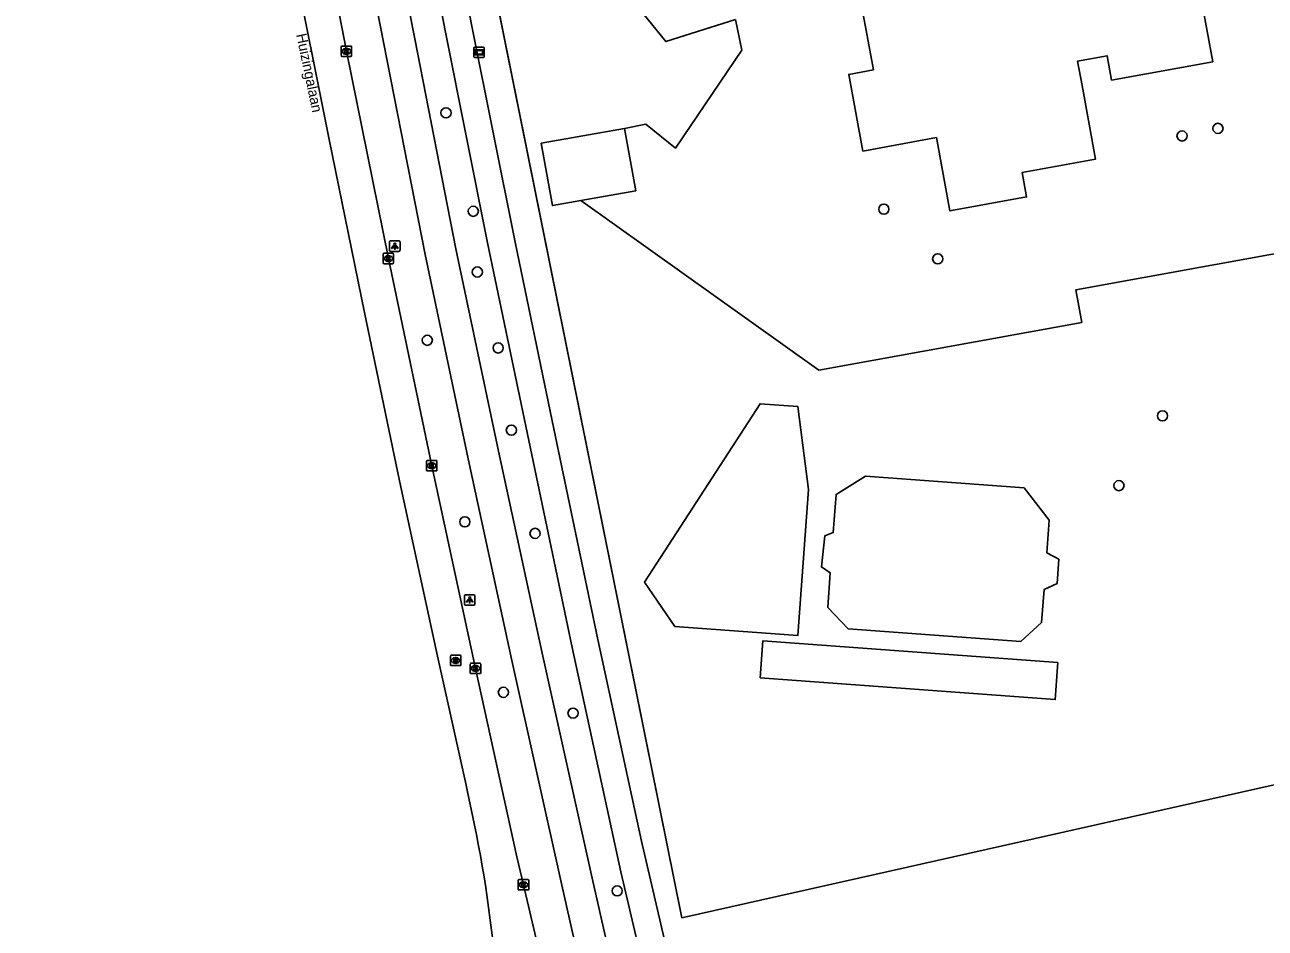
# Model space of a CAD drawing. Extents: x 159451 to 160663, y 388402 to 389723.
# Drawn here: x 159499.2 to 159618.7, y 388755.7 to 388842.8 of the extents above; entities that cross this region are included whole.
import ezdxf

# ---------------------------------------------------------------- set-up
doc = ezdxf.new("R2010")
doc.units = 0
for name, color, linetype in [('IMGEO_Boom', 7, 'Continuous'), ('IMGEO_Erf', 7, 'Continuous'), ('IMGEO_Fietspad_gesloten', 7, 'Continuous'), ('IMGEO_Groenvoorziening', 7, 'Continuous'), ('IMGEO_Hek', 7, 'Continuous'), ('IMGEO_Kolk', 7, 'Continuous'), ('IMGEO_Lichtpunt', 7, 'Continuous'), ('IMGEO_Loofbos', 7, 'Continuous'), ('IMGEO_Openbare_ruimte_label', 7, 'Continuous'), ('IMGEO_OVBaan_gesloten', 7, 'Continuous'), ('IMGEO_Pand', 7, 'Continuous'), ('IMGEO_Rijbaan_regionaal_gesloten', 7, 'Continuous'), ('IMGEO_Rioolput', 7, 'Continuous'), ('IMGEO_Terreindeel_zand', 7, 'Continuous'), ('IMGEO_Verklikker', 7, 'Continuous'), ('IMGEO_Voetpad_open', 7, 'Continuous')]:
    doc.layers.add(name, color=color, linetype=linetype)

msp = doc.modelspace()

# ---------------------------------------------------------------- linework, layer by layer
at = {"layer": 'IMGEO_Boom'}
for centre in [(159539.81, 388834.33), (159614.19, 388832.83), (159610.73, 388832.1), (159542.44, 388824.84), (159582, 388825.05), (159587.19, 388820.26), (159542.83, 388818.99), (159538.01, 388812.41), (159544.83, 388811.67), (159608.84, 388805.12), (159546.11, 388803.74), (159604.65, 388798.4), (159541.62, 388794.91), (159548.39, 388793.8), (159545.34, 388778.48), (159552.05, 388776.48), (159556.31, 388759.34)]:
    msp.add_circle(centre, 0.489, dxfattribs=at)
at = {"layer": 'IMGEO_Erf'}
for points in [[(159597.7, 388791.94), (159598.86, 388791.3), (159598.71, 388788.98), (159597.43, 388788.39), (159597.2, 388785.2), (159595.21, 388783.38), (159578.57, 388784.61), (159576.6, 388786.67), (159576.84, 388790.01), (159575.99, 388790.57), (159576.32, 388793.57), (159577.13, 388793.87), (159577.4, 388797.55), (159580.22, 388799.32), (159595.51, 388798.19), (159597.93, 388795.08), (159597.7, 388791.94)], [(159598.77, 388781.35), (159598.51, 388777.78), (159570.09, 388779.88), (159570.35, 388783.45), (159598.77, 388781.35)]]:
    msp.add_lwpolyline(points, dxfattribs=at)
at = {"layer": 'IMGEO_Fietspad_gesloten'}
for points in [[(159511.08, 388964.83), (159511.9, 388959.73), (159512.11, 388958.35), (159516.59, 388932.87), (159519.02, 388919.06), (159522.62, 388899.25), (159526.35, 388879.41), (159530.09, 388859.95), (159533.81, 388840.97), (159537.8, 388820.69), (159541.95, 388800.98), (159546.15, 388781.55), (159550.97, 388759.91), (159555.06, 388741.81), (159559.07, 388724.6), (159563.77, 388704.28), (159564.81, 388699.67)], [(159567.82, 388699.99), (159566.81, 388704.48), (159562.68, 388722.31), (159558.53, 388740.16), (159553.91, 388760.57), (159549.09, 388782.26), (159544.88, 388801.72), (159540.76, 388821.22), (159536.81, 388841.45), (159533.29, 388859.39), (159529.26, 388880.34), (159525.53, 388900.16), (159521.97, 388919.7), (159518.43, 388939.84), (159516.78, 388949.35), (159515.14, 388958.74), (159514.42, 388963.29)]]:
    msp.add_lwpolyline(points, dxfattribs=at)
at = {"layer": 'IMGEO_Groenvoorziening'}
msp.add_lwpolyline([(159574.74, 388798.04), (159573.7, 388783.95), (159561.86, 388784.82), (159558.95, 388789.11), (159570.07, 388806.3), (159573.7, 388806.03), (159574.74, 388798.04)], dxfattribs=at)
at = {"layer": 'IMGEO_Hek'}
msp.add_lwpolyline([(159678.25, 388782.74), (159562.53, 388756.76), (159538.54, 388875.75), (159538.12, 388877.8), (159532.82, 388904.1), (159527.33, 388934.89), (159516.65, 389000), (159504.91, 389075.55), (159505.31, 389078.14), (159506.99, 389079.73), (159534.92, 389087.14), (159543.41, 389088.84), (159556.65, 389090.59), (159574.7, 389093.29)], dxfattribs=at)
at = {"layer": 'IMGEO_Kolk'}
for p, q in [((159529.72, 388839.84), (159529.72, 388840.69)), ((159529.79, 388840.76), (159530.64, 388840.76)), ((159530.21, 388840.54), (159530.23, 388840.54)), ((159530.72, 388840.69), (159530.72, 388839.84)), ((159530.64, 388839.76), (159529.79, 388839.76)), ((159530.23, 388839.98), (159530.2, 388839.98)), ((159533.76, 388819.87), (159533.76, 388820.72)), ((159533.83, 388820.79), (159534.69, 388820.79)), ((159534.25, 388820.57), (159534.27, 388820.57)), ((159534.76, 388820.72), (159534.76, 388819.87)), ((159534.69, 388819.79), (159533.83, 388819.79)), ((159534.27, 388820.01), (159534.24, 388820.01)), ((159537.94, 388799.89), (159537.94, 388800.75)), ((159538.01, 388800.82), (159538.87, 388800.82)), ((159538.87, 388799.82), (159538.01, 388799.82)), ((159538.45, 388800.04), (159538.42, 388800.04)), ((159538.43, 388800.6), (159538.45, 388800.6)), ((159538.94, 388800.75), (159538.94, 388799.89)), ((159542.15, 388780.35), (159542.15, 388781.21)), ((159542.23, 388781.28), (159543.08, 388781.28)), ((159542.64, 388781.06), (159542.67, 388781.06)), ((159543.16, 388781.21), (159543.16, 388780.35)), ((159543.08, 388780.28), (159542.23, 388780.28)), ((159542.66, 388780.5), (159542.64, 388780.5)), ((159546.78, 388759.5), (159546.78, 388760.35)), ((159546.85, 388760.43), (159547.71, 388760.43)), ((159547.78, 388760.35), (159547.78, 388759.5)), ((159547.71, 388759.43), (159546.85, 388759.43)), ((159547.29, 388759.65), (159547.26, 388759.65)), ((159547.27, 388760.21), (159547.29, 388760.21))]:
    msp.add_line(p, q, dxfattribs=at)
for points in [[(159529.72, 388839.84), (159529.72, 388840.69)], [(159529.79, 388840.76), (159530.64, 388840.76)], [(159530.04, 388840.46), (159530.16, 388840.46), (159530.16, 388840.31), (159530.29, 388840.46), (159530.46, 388840.46), (159530.31, 388840.31), (159530.46, 388840.06), (159530.31, 388840.06), (159530.23, 388840.23), (159530.16, 388840.16), (159530.16, 388840.06), (159530.04, 388840.06), (159530.04, 388840.46)], [(159530.72, 388840.69), (159530.72, 388839.84)], [(159530.64, 388839.76), (159529.79, 388839.76)], [(159533.76, 388819.87), (159533.76, 388820.72)], [(159533.83, 388820.79), (159534.69, 388820.79)], [(159534.08, 388820.49), (159534.2, 388820.49), (159534.2, 388820.34), (159534.33, 388820.49), (159534.5, 388820.49), (159534.35, 388820.34), (159534.5, 388820.09), (159534.35, 388820.09), (159534.27, 388820.26), (159534.2, 388820.19), (159534.2, 388820.09), (159534.08, 388820.09), (159534.08, 388820.49)], [(159534.76, 388820.72), (159534.76, 388819.87)], [(159534.69, 388819.79), (159533.83, 388819.79)], [(159537.94, 388799.89), (159537.94, 388800.75)], [(159538.01, 388800.82), (159538.87, 388800.82)], [(159538.87, 388799.82), (159538.01, 388799.82)], [(159538.26, 388800.52), (159538.38, 388800.52), (159538.38, 388800.37), (159538.51, 388800.52), (159538.68, 388800.52), (159538.53, 388800.37), (159538.68, 388800.12), (159538.53, 388800.12), (159538.45, 388800.28), (159538.38, 388800.22), (159538.38, 388800.12), (159538.26, 388800.12), (159538.26, 388800.52)], [(159538.94, 388800.75), (159538.94, 388799.89)], [(159542.15, 388780.35), (159542.15, 388781.21)], [(159542.23, 388781.28), (159543.08, 388781.28)], [(159542.47, 388780.98), (159542.6, 388780.98), (159542.6, 388780.83), (159542.73, 388780.98), (159542.89, 388780.98), (159542.75, 388780.83), (159542.9, 388780.58), (159542.75, 388780.58), (159542.66, 388780.75), (159542.6, 388780.68), (159542.6, 388780.58), (159542.47, 388780.58), (159542.47, 388780.98)], [(159543.16, 388781.21), (159543.16, 388780.35)], [(159543.08, 388780.28), (159542.23, 388780.28)], [(159546.78, 388759.5), (159546.78, 388760.35)], [(159546.85, 388760.43), (159547.71, 388760.43)], [(159547.78, 388760.35), (159547.78, 388759.5)], [(159547.71, 388759.43), (159546.85, 388759.43)], [(159547.1, 388760.13), (159547.22, 388760.13), (159547.22, 388759.98), (159547.35, 388760.13), (159547.52, 388760.13), (159547.37, 388759.98), (159547.52, 388759.73), (159547.37, 388759.73), (159547.29, 388759.89), (159547.22, 388759.83), (159547.22, 388759.73), (159547.1, 388759.73), (159547.1, 388760.13)]]:
    msp.add_lwpolyline(points, dxfattribs=at)
for centre, start, end in [((159529.79, 388840.69), 91.552, 178.448), ((159529.79, 388840.69), 91.552, 178.448), ((159530.64, 388840.69), 1.552, 88.448), ((159530.64, 388840.69), 1.552, 88.448), ((159529.79, 388839.84), 181.552, 268.448), ((159529.79, 388839.84), 181.552, 268.448), ((159530.64, 388839.84), 271.552, 358.448), ((159530.64, 388839.84), 271.552, 358.448), ((159533.83, 388820.72), 91.552, 178.448), ((159533.83, 388820.72), 91.552, 178.448), ((159534.68, 388820.72), 1.552, 88.448), ((159534.68, 388820.72), 1.552, 88.448), ((159533.83, 388819.87), 181.552, 268.448), ((159533.83, 388819.87), 181.552, 268.448), ((159534.68, 388819.87), 271.552, 358.448), ((159534.68, 388819.87), 271.552, 358.448), ((159538.02, 388800.74), 91.552, 178.448), ((159538.02, 388800.74), 91.552, 178.448), ((159538.02, 388799.89), 181.552, 268.448), ((159538.02, 388799.89), 181.552, 268.448), ((159538.86, 388800.74), 1.552, 88.448), ((159538.86, 388800.74), 1.552, 88.448), ((159538.86, 388799.89), 271.552, 358.448), ((159538.86, 388799.89), 271.552, 358.448), ((159542.23, 388781.21), 91.552, 178.448), ((159542.23, 388781.21), 91.552, 178.448), ((159543.08, 388781.21), 1.552, 88.448), ((159543.08, 388781.21), 1.552, 88.448), ((159542.23, 388780.36), 181.552, 268.448), ((159542.23, 388780.36), 181.552, 268.448), ((159543.08, 388780.36), 271.552, 358.448), ((159543.08, 388780.36), 271.552, 358.448), ((159546.85, 388760.35), 91.552, 178.448), ((159546.85, 388760.35), 91.552, 178.448), ((159547.7, 388760.35), 1.552, 88.448), ((159547.7, 388760.35), 1.552, 88.448), ((159546.85, 388759.5), 181.552, 268.448), ((159546.85, 388759.5), 181.552, 268.448), ((159547.7, 388759.5), 271.552, 358.448), ((159547.7, 388759.5), 271.552, 358.448)]:
    msp.add_arc(centre, 0.0765, start, end, dxfattribs=at)
for centre, major_axis, ratio, start_param, end_param in [((159530.2, 388840.26), (-0.387, 0.002), 0.722429, 4.712389, 7.853982), ((159530.23, 388840.26), (-0.39, 0.002), 0.717154, 1.570796, 4.712389), ((159534.25, 388820.29), (-0.387, 0.002), 0.722429, 4.712389, 7.853982), ((159534.27, 388820.29), (-0.39, 0.002), 0.717154, 1.570796, 4.712389), ((159538.43, 388800.32), (-0.387, 0.002), 0.722429, 4.712389, 7.853982), ((159538.45, 388800.32), (-0.39, 0.002), 0.717154, 1.570796, 4.712389), ((159542.64, 388780.78), (-0.387, 0.002), 0.722429, 4.712389, 7.853982), ((159542.67, 388780.78), (-0.39, 0.002), 0.717154, 1.570796, 4.712389), ((159547.27, 388759.93), (-0.387, 0.002), 0.722429, 4.712389, 7.853982), ((159547.29, 388759.93), (-0.39, 0.002), 0.717154, 1.570796, 4.712389)]:
    msp.add_ellipse(centre, major_axis=major_axis, ratio=ratio, start_param=start_param, end_param=end_param, dxfattribs=at)
at = {"layer": 'IMGEO_Lichtpunt'}
for p, q in [((159534.38, 388821.89), (159534.38, 388821.08)), ((159534.38, 388821.89), (159534.38, 388821.08)), ((159535.28, 388821.98), (159534.47, 388821.98)), ((159535.28, 388821.98), (159534.47, 388821.98)), ((159535.38, 388821.08), (159535.38, 388821.89)), ((159535.38, 388821.08), (159535.38, 388821.89)), ((159534.47, 388820.98), (159535.28, 388820.98)), ((159534.47, 388820.98), (159535.28, 388820.98)), ((159541.6, 388787.79), (159541.6, 388786.99)), ((159541.6, 388787.79), (159541.6, 388786.99)), ((159542.5, 388787.89), (159541.69, 388787.89)), ((159542.5, 388787.89), (159541.69, 388787.89)), ((159542.59, 388786.99), (159542.59, 388787.79)), ((159542.59, 388786.99), (159542.59, 388787.79)), ((159541.69, 388786.89), (159542.5, 388786.89)), ((159541.69, 388786.89), (159542.5, 388786.89))]:
    msp.add_line(p, q, dxfattribs=at)
for points in [[(159534.75, 388821.55), (159534.79, 388821.52), (159534.61, 388821.26), (159534.57, 388821.29), (159534.75, 388821.55)], [(159534.86, 388821.5), (159534.9, 388821.5), (159534.9, 388821.18), (159534.86, 388821.18), (159534.86, 388821.5)], [(159534.97, 388821.52), (159535, 388821.55), (159535.19, 388821.29), (159535.15, 388821.26), (159534.97, 388821.52)], [(159541.97, 388787.46), (159542.01, 388787.43), (159541.82, 388787.17), (159541.78, 388787.19), (159541.97, 388787.46)], [(159542.07, 388787.41), (159542.12, 388787.41), (159542.12, 388787.09), (159542.07, 388787.09), (159542.07, 388787.41)], [(159542.18, 388787.43), (159542.22, 388787.46), (159542.41, 388787.19), (159542.37, 388787.17), (159542.18, 388787.43)]]:
    msp.add_lwpolyline(points, dxfattribs=at)
for centre in [(159534.88, 388821.68), (159542.1, 388787.59)]:
    msp.add_circle(centre, 0.0994, dxfattribs=at)
for centre, start, end in [((159534.47, 388821.89), 90, 180), ((159534.47, 388821.89), 90, 180), ((159535.28, 388821.89), 0, 90), ((159535.28, 388821.89), 0, 90), ((159534.47, 388821.08), 180, 270), ((159534.47, 388821.08), 180, 270), ((159535.28, 388821.08), 270, 0), ((159535.28, 388821.08), 270, 360), ((159541.69, 388787.79), 90, 180), ((159541.69, 388787.79), 90, 180), ((159542.5, 388787.79), 0, 90), ((159542.5, 388787.79), 0, 90), ((159541.69, 388786.99), 180, 270), ((159541.69, 388786.99), 180, 270), ((159542.5, 388786.99), 270, 0), ((159542.5, 388786.99), 270, 360)]:
    msp.add_arc(centre, 0.0946, start, end, dxfattribs=at)
at = {"layer": 'IMGEO_Loofbos'}
msp.add_lwpolyline([(159538.55, 388875.67), (159562.53, 388756.76), (159678.25, 388782.74), (159689.42, 388833.24), (159688.56, 388837.48), (159685.61, 388852.04)], dxfattribs=at)
at = {"layer": 'IMGEO_OVBaan_gesloten'}
for points in [[(159499.23, 388994.84), (159500.03, 388990.58), (159500.27, 388989.26), (159503.76, 388967.73), (159507.6, 388945.01), (159510.84, 388926.49), (159514.58, 388905.28), (159517.66, 388888.54), (159521.55, 388867.6), (159524.96, 388849.75), (159528.54, 388831.76), (159531.95, 388815.1), (159535.34, 388798.85), (159538.98, 388781.96), (159541.75, 388769.52)], [(159543.64, 388759.66), (159544.31, 388754.59)]]:
    msp.add_lwpolyline(points, dxfattribs=at)
msp.add_arc((159393.65, 388735.92), 151.86, 8.996, 12.7816, dxfattribs=at)
at = {"layer": 'IMGEO_Pand'}
for points in [[(159612.61, 388845.16), (159613.69, 388839.26), (159603.94, 388837.48), (159603.51, 388839.83), (159600.67, 388839.31), (159601.1, 388836.96), (159602.4, 388829.87), (159595.32, 388828.57), (159595.75, 388826.23), (159588.36, 388824.87), (159587.06, 388831.95), (159579.98, 388830.65), (159578.62, 388838.04), (159580.99, 388838.48), (159579.69, 388845.56)], [(159552.81, 388825.88), (159550.06, 388825.39), (159548.99, 388831.4), (159557.02, 388832.83)], [(159557.02, 388832.83), (159558.09, 388826.82), (159552.81, 388825.88)]]:
    msp.add_lwpolyline(points, dxfattribs=at)
at = {"layer": 'IMGEO_Rijbaan_regionaal_gesloten'}
msp.add_lwpolyline([(159561.59, 388698.98), (159561.07, 388701.2), (159560.62, 388703.15), (159556.37, 388721.14), (159551.72, 388741.02), (159547.28, 388759.93), (159546.64, 388762.61), (159542.65, 388780.78), (159538.44, 388800.32), (159534.26, 388820.29), (159530.22, 388840.26), (159526.53, 388859.3), (159522.9, 388878.37), (159519.19, 388898.44), (159515.61, 388918.53), (159512.08, 388938.65), (159508.7, 388957.75), (159508.35, 388959.87), (159507.46, 388965.11)], dxfattribs=at)
at = {"layer": 'IMGEO_Rioolput'}
for p, q in [((159540.24, 388781.13), (159540.24, 388781.98)), ((159540.32, 388782.06), (159541.17, 388782.06)), ((159540.73, 388781.83), (159540.76, 388781.83)), ((159541.24, 388781.98), (159541.24, 388781.13)), ((159541.17, 388781.05), (159540.32, 388781.05)), ((159540.75, 388781.28), (159540.73, 388781.28))]:
    msp.add_line(p, q, dxfattribs=at)
for points in [[(159540.24, 388781.13), (159540.24, 388781.98)], [(159540.32, 388782.06), (159541.17, 388782.06)], [(159541.24, 388781.98), (159541.24, 388781.13)], [(159541.17, 388781.05), (159540.32, 388781.05)], [(159540.83, 388781.75), (159540.58, 388781.75), (159540.58, 388781.35)], [(159540.58, 388781.35), (159540.7, 388781.35), (159540.7, 388781.52), (159540.71, 388781.52)], [(159540.76, 388781.67), (159540.7, 388781.67), (159540.7, 388781.59)], [(159540.7, 388781.59), (159540.75, 388781.59)], [(159540.76, 388781.49), (159540.83, 388781.35), (159540.97, 388781.35), (159540.91, 388781.48)]]:
    msp.add_lwpolyline(points, dxfattribs=at)
for centre, radius, start, end in [((159540.32, 388781.98), 0.0765, 91.552, 178.448), ((159540.32, 388781.98), 0.0765, 91.552, 178.448), ((159541.17, 388781.98), 0.0765, 1.552, 88.448), ((159541.17, 388781.98), 0.0765, 1.552, 88.448), ((159540.32, 388781.13), 0.0765, 181.552, 268.448), ((159540.32, 388781.13), 0.0765, 181.552, 268.448), ((159540.71, 388781.46), 0.0533, 26.0293, 88.6989), ((159540.74, 388781.78), 0.19, 274.7715, 282.9687), ((159540.76, 388781.58), 0.0964, 77.0061, 93.1865), ((159540.78, 388781.63), 0.0378, 276.6634, 79.6772), ((159540.83, 388781.64), 0.109, 350.3612, 89.416), ((159540.83, 388781.64), 0.112, 277.5842, 350.9817), ((159540.81, 388781.43), 0.108, 29.5134, 73.7905), ((159541.17, 388781.13), 0.0765, 271.552, 358.448), ((159541.17, 388781.13), 0.0765, 271.552, 358.448)]:
    msp.add_arc(centre, radius, start, end, dxfattribs=at)
for centre, major_axis, ratio, start_param, end_param in [((159540.73, 388781.55), (-0.387, 0.002), 0.722429, 4.712389, 7.853982), ((159540.75, 388781.55), (-0.39, 0.002), 0.717154, 1.570796, 4.712389)]:
    msp.add_ellipse(centre, major_axis=major_axis, ratio=ratio, start_param=start_param, end_param=end_param, dxfattribs=at)
at = {"layer": 'IMGEO_Terreindeel_zand'}
msp.add_lwpolyline([(159567.72, 388843.34), (159560.98, 388841.19), (159555.74, 388847.74), (159560.59, 388852.46)], dxfattribs=at)
at = {"layer": 'IMGEO_Verklikker'}
for p, q in [((159542.5, 388839.77), (159542.5, 388840.57)), ((159542.5, 388840.57), (159542.5, 388839.77)), ((159542.6, 388840.67), (159543.39, 388840.67)), ((159543.39, 388840.67), (159542.6, 388840.67)), ((159543.49, 388840.57), (159543.49, 388839.77)), ((159543.49, 388839.77), (159543.49, 388840.57)), ((159543.39, 388839.67), (159542.6, 388839.67)), ((159542.6, 388839.67), (159543.39, 388839.67))]:
    msp.add_line(p, q, dxfattribs=at)
for points in [[(159542.6, 388840.4), (159543.39, 388840.4), (159543.39, 388839.93), (159542.6, 388839.93), (159542.6, 388840.4)], [(159542.66, 388840.33), (159542.66, 388840), (159543.32, 388840), (159543.32, 388840.33), (159542.66, 388840.33)]]:
    msp.add_lwpolyline(points, dxfattribs=at)
for centre, start, end in [((159542.6, 388840.57), 90, 180), ((159542.6, 388840.57), 90, 180), ((159543.39, 388840.57), 0, 90), ((159543.39, 388840.57), 360, 90), ((159542.6, 388839.77), 180, 270), ((159542.6, 388839.77), 180, 270), ((159543.39, 388839.77), 270, 0), ((159543.39, 388839.77), 270, 0)]:
    msp.add_arc(centre, 0.1, start, end, dxfattribs=at)
at = {"layer": 'IMGEO_Voetpad_open'}
for points in [[(159513.62, 388987.78), (159514.23, 388982.9), (159514.92, 388978.44), (159519.79, 388949.99), (159521.43, 388940.62), (159524.98, 388920.29), (159528.4, 388901.45), (159532.3, 388880.81), (159535.83, 388862.33), (159539.76, 388842.11), (159543.82, 388821.79), (159547.49, 388804.12), (159551.96, 388782.81), (159556.66, 388761.18), (159560.7, 388743.94), (159569.8, 388705.34), (159570.66, 388701.6), (159570.89, 388700.66)], [(159538.55, 388875.67), (159536.01, 388875.2), (159538.42, 388862.69), (159542.32, 388842.53), (159546.47, 388821.86), (159550.03, 388804.64), (159554.44, 388783.56), (159558.65, 388764.13), (159562.92, 388745.78), (159569.25, 388718.9), (159573.34, 388701.53)], [(159567.72, 388843.34), (159568.33, 388840.38), (159561.91, 388830.94), (159559.07, 388833.23), (159557.02, 388832.83)], [(159552.81, 388825.88), (159575.75, 388809.53), (159601.06, 388814.13), (159600.49, 388817.26), (159632.91, 388823.15), (159637.51, 388830.55), (159652.89, 388824.78)]]:
    msp.add_lwpolyline(points, dxfattribs=at)

# ---------------------------------------------------------------- texts
at = {"layer": 'IMGEO_Openbare_ruimte_label'}
msp.add_text('Huizingalaan', height=1, rotation=281.7706, dxfattribs=at).set_placement((159525.37, 388841.87))

doc.saveas('drawing.dxf')
